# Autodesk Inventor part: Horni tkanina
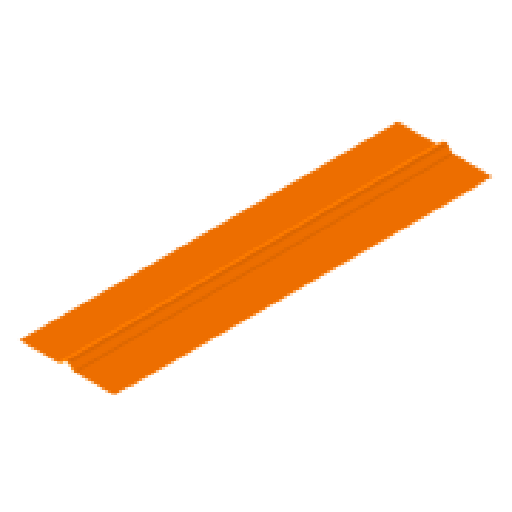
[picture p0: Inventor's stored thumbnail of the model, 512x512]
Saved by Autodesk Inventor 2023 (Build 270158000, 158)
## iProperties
Created: 2025-03
Part Number: Horni tkanina
Material: Všeobecné
Document SubType Name: Modeling
Designer: tomik
Density: 1 g/cm^3
Appearance: Výchozí(1)
Author: tomik
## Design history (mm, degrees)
sketch "Náčrt1"
  geometry: L1 (0, 0)-(0, 10.449); L2 (0, 0)-(6.785, 0); L3 (0, 0)-(0, 4); L4 (0, 0)-(4, 0); L5 (3.268, 0.732)-(0, 4); L6 (0, 0)-(-6.785, 0); L7 (0, 0)-(-4, 0); L8 (-3.268, 0.732)-(0, 4); A1 r 2.5 centre (5.036, 2.5) between (3.268, 0.732) and (5.036, 0); A2 r 2.5 centre (-5.036, 2.5) between (-5.036, 0) and (-3.268, 0.732)
  constraints: 16 end point, 5 point on line, 5 symmetric about line, 4 point on circle, 2 centre point, 2 tangent, 1 horizontal, 1 vertical, 1 other
  dimensions: "d0" = 4 distance of L1.start L3.end; "d3" = 4 distance of L1.start L4.end; "d4" = 5 diameter of A1; "d5" = 5.03553 distance from line of A1.end L1
extrude "Vysunutí1" new body sketch "Náčrt1" distance "d6" = 200; taper "d7" = 0 deg
fillet "Zaoblení1" dims "d8" = 2
feature "Zesílit1" dims "d9" = 0.6, "d10" = 2
sketch "Náčrt2"
  geometry: 1 further point
node "Pracovní rovina1"
sketch "Náčrt3"
  geometry: L1 (0, 0)-(0, 200) reference; L2 (0, 0)-(0.6, 0) reference; L3 (0, 0)-(0, 200) reference; L4 (0, 0)-(0.6, 0) reference; L5 (0.6, 0)-(0.6, 200) reference; L6 (0, 200)-(0.6, 200) reference; 2 further points
extrude "Vysunutí2" join sketch "Náčrt3" stored distance "d12" = 200; taper "d13" = 0 deg
mirror "Zrcadlit1"
sketch "Náčrt4"
  geometry: L1 (0, 0)-(19.964, 0) reference; L2 (50, 200)-(50, 0) reference; L3 (0, 0)-(50, 0); L4 (50, 0)-(50, 8); L5 (50, 8)-(0, 8); L6 (0, 8)-(0, 0); 3 further points
  constraints: 8 end point, 2 parallel, 1 horizontal, 1 perpendicular, 1 point on line
  dimensions: "d14" = 8 distance between parallel lines of L3 L5
extrude "Vysunutí3" cut sketch "Náčrt4" distance "d15" = 0.5; taper "d16" = 0 deg
node "Pracovní rovina2"
fillet "Zaoblení2" dims "d18" = 0.8
chamfer "Zkosení1" distance "d19" = 0.4999; stored, may be unused: second distance "d20" = 2, angle "d21" = 45 deg
mirror "Zrcadlit2"
node "Těleso1"
node "Těleso3"
node "Promítnutá smyčka1"
node "Pracovní rovina3"
other parameters: "d11" = 25
